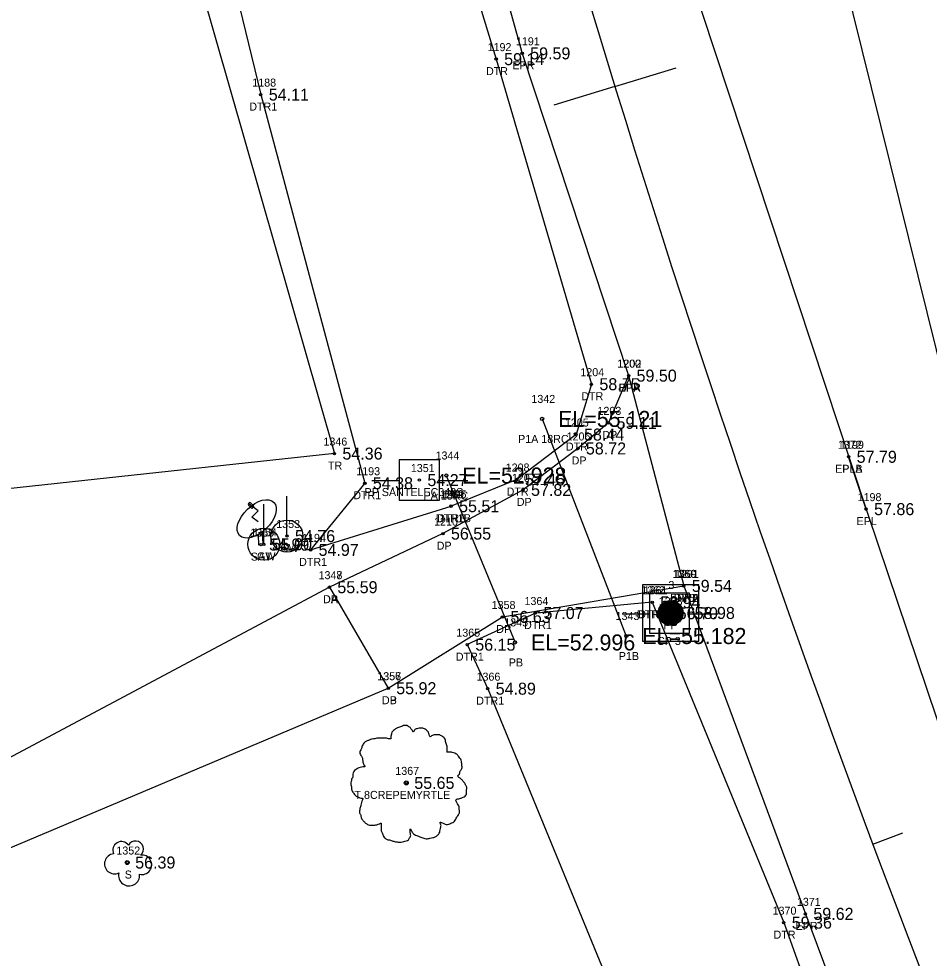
# Model space of a CAD drawing. Extents: x 2396531 to 2397633, y 770203 to 772837.
# Drawn here: x 2397010.1 to 2397123.8, y 771166.1 to 771283.5 of the extents above; entities that cross this region are included whole.
import ezdxf

# ---------------------------------------------------------------- set-up
doc = ezdxf.new("R2010")
doc.units = 0
for name, color, linetype in [('RD_EX_BldgApp', 7, 'Continuous'), ('RD_EX_BldgApp_txCode', 7, 'Continuous'), ('RD_EX_DR_Pipe', 7, 'Continuous'), ('RD_EX_DR_Pipe_txCode', 7, 'Continuous'), ('RD_EX_Driveway', 7, 'Continuous'), ('RD_EX_Driveway_txCode', 7, 'Continuous'), ('RD_EX_H2O', 7, 'Continuous'), ('RD_EX_H2O_txCode', 7, 'Continuous'), ('RD_EX_Road', 7, 'Continuous'), ('RD_EX_Road_txCode', 7, 'Continuous'), ('RD_EX_TX_BldgApp_ELEV', 7, 'Continuous'), ('RD_EX_TX_Driveway_ELEV', 7, 'Continuous'), ('RD_EX_TX_H2O_ELEV', 7, 'Continuous'), ('RD_EX_TX_Road_ELEV', 7, 'Continuous'), ('RD_EX_TX_UT_ELEV', 7, 'Continuous'), ('RD_EX_TX_VEG_ELEV', 7, 'Continuous'), ('RD_EX_UT', 7, 'Continuous'), ('RD_EX_UT_txCode', 7, 'Continuous'), ('RD_EX_VEG', 7, 'Continuous'), ('RD_EX_VEG_txCode', 7, 'Continuous'), ('RD_HC_Cl', 7, 'Continuous'), ('RD_HC_Data_Tic', 7, 'Continuous'), ('RD_HC_Survey', 7, 'Continuous'), ('RD_HC_Survey_ELEV', 7, 'Continuous'), ('RD_HC_Survey_txCode', 7, 'Continuous'), ('RD_SMD_Locator', 7, 'Continuous'), ('RD_TX_Pipe_ElevEX', 7, 'Continuous')]:
    doc.layers.add(name, color=color, linetype=linetype)

msp = doc.modelspace()

# ---------------------------------------------------------------- linework, layer by layer
at = {"layer": 'RD_EX_BldgApp'}
for p, q in [((2397039.18, 771222.31), (2397038.79, 771222.69)), ((2397039.97, 771221.99), (2397038.86, 771222.83)), ((2397039.03, 771222.99), (2397039.46, 771222.62)), ((2397039.07, 771222.73), (2397039.07, 771222.73)), ((2397039.18, 771222.71), (2397039.18, 771222.71)), ((2397039.46, 771222.62), (2397039.18, 771222.31)), ((2397039.2, 771221.22), (2397039.97, 771221.99)), ((2397039.97, 771220.61), (2397039.2, 771221.22)), ((2397039.97, 771219.05), (2397040.04, 771217.7)), ((2397040.5, 771219.33), (2397040.58, 771217.88))]:
    msp.add_line(p, q, dxfattribs=at)
msp.add_ellipse((2397039.81, 771220.99), major_axis=(-2.15, -2.07), ratio=0.564687, dxfattribs=at)
msp.add_ellipse((2397038.92, 771222.84), major_axis=(0.099, 0.164), ratio=0.846225, start_param=6.138676, end_param=9.218032, dxfattribs=at)
at = {"layer": 'RD_EX_DR_Pipe'}
for p, q in [((2397075.46, 771233.48), (2397085.98, 771206.36)), ((2397063.49, 771226.41), (2397072.08, 771205.56))]:
    msp.add_line(p, q, dxfattribs=at)
at = {"layer": 'RD_EX_Driveway'}
for p, q in [((2397048.88, 771212.46), (2397001.22, 771187.05)), ((2397003.63, 771177.66), (2397056.23, 771199.84))]:
    msp.add_line(p, q, dxfattribs=at)
msp.add_lwpolyline([(2397086.26, 771238.89), (2397083.76, 771232.99), (2397079.93, 771229.79), (2397073.08, 771224.62), (2397063.07, 771219.15), (2397048.88, 771212.46), (2397056.23, 771199.84), (2397070.51, 771208.74), (2397093.16, 771212.62)], dxfattribs=at)
at = {"layer": 'RD_EX_H2O'}
for points in [[(2397018.97, 771356.22), (2397026.87, 771329.32), (2397040.31, 771274), (2397053.31, 771225.45), (2397046.53, 771217.12), (2397064.09, 771222.58)], [(2397050.12, 771356.42), (2397048.45, 771348.09), (2397069.72, 771278.43), (2397081.62, 771237.82), (2397079.7, 771231.53), (2397072.3, 771225.91), (2397064.09, 771222.58)], [(2397089.23, 771210.58), (2397074.63, 771209.23), (2397066.11, 771205.28), (2397068.66, 771199.78), (2397083.54, 771163.57), (2397098.64, 771123.33)], [(2397089.23, 771210.58), (2397105.65, 771170.55), (2397119.48, 771131.94), (2397110.45, 771123.52), (2397093.81, 771116.52), (2397098.64, 771123.33)]]:
    msp.add_lwpolyline(points, dxfattribs=at)
at = {"layer": 'RD_EX_Road'}
for points in [[(2397072.37, 771363.69), (2397093.67, 771289.64), (2397115.94, 771222.21), (2397113.76, 771228.75)], [(2397051, 771358.07), (2397072.97, 771279.15), (2397086.26, 771238.89), (2397093.16, 771212.62)], [(2397113.76, 771228.75), (2397130.87, 771177.98), (2397154.19, 771118.49), (2397170.38, 771081.25), (2397178.53, 771063.49), (2397207.96, 771004.56), (2397238.54, 770949.11), (2397245.72, 770936.59), (2397280.76, 770876.73)], [(2397093.16, 771212.62), (2397108.35, 771171.65), (2397122.66, 771133.29), (2397131.66, 771109.5), (2397159.86, 771046.96), (2397187.02, 770992.86), (2397227.29, 770920.43), (2397260.16, 770864.73)]]:
    msp.add_lwpolyline(points, dxfattribs=at)
at = {"layer": 'RD_EX_UT'}
for p, q in [((2397062.62, 771228.35), (2397057.62, 771228.35)), ((2397057.62, 771228.35), (2397057.62, 771223.35)), ((2397062.62, 771223.35), (2397062.62, 771228.35)), ((2397054.19, 771225.79), (2397057.66, 771225.79)), ((2397062.55, 771225.79), (2397066.19, 771225.79)), ((2397043.58, 771218.85), (2397043.58, 771223.85)), ((2397057.62, 771223.35), (2397062.62, 771223.35)), ((2397040.69, 771217.82), (2397040.69, 771222.82)), ((2397093.89, 771211.72), (2397088.89, 771211.72)), ((2397088.89, 771211.72), (2397088.89, 771206.72)), ((2397093.89, 771206.72), (2397093.89, 771211.72)), ((2397085.46, 771209.15), (2397088.92, 771209.15)), ((2397093.82, 771209.15), (2397097.46, 771209.15)), ((2397088.89, 771206.72), (2397093.89, 771206.72))]:
    msp.add_line(p, q, dxfattribs=at)
for centre in [(2397040.69, 771217.82), (2397043.58, 771218.85)]:
    msp.add_circle(centre, 2, dxfattribs=at)
at = {"layer": 'RD_EX_VEG'}
for points in [[(2396666.35, 772324.52), (2396746.5, 772348.13), (2396878.43, 771953.6), (2396907.83, 771806.94), (2396910.04, 771736.08), (2396945.43, 771592.11), (2397049.51, 771229.15), (2396980.16, 771221.67)], [(2397137.17, 771710.16), (2397010.6, 771680.28), (2397078.29, 771429.37), (2397127.02, 771232.69), (2397127.02, 771232.69), (2397166.52, 771123.83), (2397178.02, 771098.29), (2397254.06, 771102.5)]]:
    msp.add_lwpolyline(points, dxfattribs=at)
for centre, radius in [((2397058.49, 771188.01), 0.25), ((2397058.48, 771187.99), 0.0001), ((2397023.62, 771178.06), 0.25)]:
    msp.add_circle(centre, radius, dxfattribs=at)
for centre, radius, start, end in [((2397022.9, 771179.6), 1.08, 34.9763, 204.756), ((2397024.66, 771179.76), 0.995, 308.7626, 152.0467), ((2397022.05, 771177.9), 1.26, 96.4518, 294.734), ((2397025.46, 771177.78), 1.22, 256.5667, 98.1046), ((2397023.86, 771176.46), 1.32, 166.8827, 5.7589)]:
    msp.add_arc(centre, radius, start, end, dxfattribs=at)
for points in [[(2397058.62, 771195.18), (2397058.32, 771195.2), (2397058, 771195.1), (2397057.75, 771195), (2397057.52, 771194.93), (2397057.3, 771194.83), (2397057, 771194.65), (2397056.77, 771194.45), (2397056.65, 771194.2), (2397056.6, 771193.98), (2397056.55, 771193.7), (2397056.55, 771193.53), (2397056.42, 771193.5), (2397056.27, 771193.53), (2397056.02, 771193.6), (2397055.77, 771193.6), (2397055.52, 771193.6), (2397055.17, 771193.58), (2397054.83, 771193.58), (2397054.55, 771193.53), (2397054.23, 771193.48), (2397053.85, 771193.35), (2397053.5, 771193.23), (2397053.2, 771192.98), (2397052.95, 771192.5), (2397052.83, 771192.15), (2397052.68, 771191.9), (2397052.83, 771191.45), (2397053, 771191.11), (2397053.03, 771190.91), (2397053.1, 771190.48), (2397053.2, 771190.26), (2397053.33, 771190.06), (2397053.25, 771190.03), (2397052.88, 771189.98), (2397052.58, 771189.88), (2397052.15, 771189.66), (2397051.93, 771189.43), (2397051.83, 771189.11), (2397051.8, 771188.76), (2397051.7, 771188.56), (2397051.63, 771188.28), (2397051.6, 771188.21), (2397051.55, 771187.88), (2397051.65, 771187.43), (2397051.68, 771187.08), (2397051.8, 771186.86), (2397051.95, 771186.68), (2397052.13, 771186.43), (2397052.53, 771186.21), (2397052.85, 771186.11), (2397053.05, 771186.08), (2397052.88, 771185.58), (2397052.83, 771185.23), (2397052.7, 771184.83), (2397052.7, 771184.76), (2397052.65, 771184.28), (2397052.8, 771183.96), (2397052.88, 771183.58), (2397053.05, 771183.36), (2397053.33, 771183.06), (2397053.65, 771182.83), (2397054.15, 771182.71), (2397054.55, 771182.73), (2397055.13, 771182.91), (2397055.37, 771182.98), (2397055.35, 771182.81), (2397055.37, 771182.43), (2397055.37, 771182.01), (2397055.52, 771181.68), (2397055.62, 771181.41), (2397055.77, 771181.16), (2397056.1, 771180.93), (2397056.5, 771180.86), (2397056.92, 771180.71), (2397057.37, 771180.63), (2397057.87, 771180.61), (2397058.47, 771180.76), (2397058.75, 771180.88), (2397058.85, 771181.06), (2397059.05, 771181.43), (2397059, 771181.66), (2397059.02, 771182.26), (2397059.12, 771182.08), (2397059.3, 771181.73), (2397059.8, 771181.43), (2397060.2, 771181.26), (2397060.67, 771181.11), (2397060.97, 771181.03), (2397061.45, 771181.11), (2397061.82, 771181.18), (2397062.2, 771181.31), (2397062.5, 771181.58), (2397062.67, 771181.86), (2397062.72, 771182.13), (2397062.8, 771182.51), (2397062.85, 771182.68)], [(2397062.85, 771182.68), (2397062.77, 771182.86), (2397062.72, 771183.11), (2397062.8, 771183.08), (2397062.97, 771183.03), (2397063.25, 771182.91), (2397063.47, 771182.83), (2397063.8, 771182.86), (2397064.07, 771182.96), (2397064.52, 771183.23), (2397064.8, 771183.71), (2397065.07, 771184.11), (2397065.15, 771184.43), (2397065.1, 771184.66), (2397065.07, 771185.16), (2397064.87, 771185.41), (2397064.82, 771185.53), (2397064.72, 771185.93), (2397064.8, 771185.98), (2397065.07, 771186.03), (2397065.45, 771186.16), (2397065.72, 771186.28), (2397065.95, 771186.46), (2397066.02, 771186.68), (2397066, 771187.08), (2397066.05, 771187.48), (2397065.97, 771187.63), (2397065.87, 771187.78), (2397065.8, 771187.98), (2397065.65, 771188.13), (2397065.55, 771188.28), (2397065.45, 771188.38), (2397065.32, 771188.53), (2397065.15, 771188.66), (2397065, 771188.71), (2397064.95, 771188.86), (2397065.1, 771189.06), (2397065.15, 771189.16), (2397065.17, 771189.38), (2397065.4, 771189.73), (2397065.45, 771190.13), (2397065.4, 771190.56), (2397065.35, 771190.83), (2397065.2, 771191.11), (2397065, 771191.35), (2397064.87, 771191.53), (2397064.7, 771191.65), (2397064.37, 771191.78), (2397064.12, 771191.83), (2397063.77, 771191.83), (2397063.57, 771191.88), (2397063.6, 771191.93), (2397063.6, 771192.08), (2397063.6, 771192.35), (2397063.52, 771192.8), (2397063.37, 771193.3), (2397063.37, 771193.33), (2397063.27, 771193.58), (2397063.05, 771193.78), (2397062.87, 771193.88), (2397062.67, 771194), (2397062.42, 771194.03), (2397062.12, 771194.03), (2397061.85, 771193.98), (2397061.65, 771193.88), (2397061.47, 771193.75), (2397061.4, 771193.9), (2397061.3, 771194.2), (2397061.25, 771194.35), (2397061.1, 771194.53), (2397060.87, 771194.73), (2397060.42, 771194.85), (2397059.8, 771194.78), (2397059.5, 771194.58), (2397059.35, 771194.4), (2397059.3, 771194.53), (2397059.1, 771194.73), (2397059, 771194.9), (2397058.82, 771195.03), (2397058.67, 771195.13), (2397058.57, 771195.18)]]:
    msp.add_spline(points, degree=3, dxfattribs=at)
at = {"layer": 'RD_HC_Cl'}
msp.add_arc((2398682.18, 771766.08), 1671.39, 194.59125, 211.50817, dxfattribs=at)
at = {"layer": 'RD_HC_Data_Tic'}
for p, q in [((2397084.56, 771275.01), (2397092.21, 771277.36)), ((2397084.56, 771275.01), (2397076.92, 771272.66)), ((2397116.79, 771180.36), (2397120.53, 771181.76))]:
    msp.add_line(p, q, dxfattribs=at)
at = {"layer": 'RD_HC_Survey'}
for p, q in [((2397090.51, 771208.06), (2397090.51, 771210.42)), ((2397090.56, 771208.02), (2397090.56, 771210.46)), ((2397090.61, 771207.98), (2397090.61, 771210.5)), ((2397090.66, 771207.94), (2397090.66, 771210.53)), ((2397090.71, 771207.91), (2397090.71, 771210.56)), ((2397090.76, 771207.88), (2397090.76, 771210.59)), ((2397090.81, 771207.86), (2397090.81, 771210.62)), ((2397090.86, 771207.83), (2397090.86, 771210.64)), ((2397090.91, 771207.81), (2397090.91, 771210.67)), ((2397090.96, 771207.79), (2397090.96, 771210.69)), ((2397091.01, 771207.77), (2397091.01, 771210.71)), ((2397091.06, 771207.75), (2397091.06, 771210.72)), ((2397091.11, 771207.74), (2397091.11, 771210.74)), ((2397091.16, 771207.73), (2397091.16, 771210.75)), ((2397091.21, 771207.71), (2397091.21, 771210.76)), ((2397091.26, 771207.7), (2397091.26, 771210.77)), ((2397091.31, 771207.7), (2397091.31, 771210.78)), ((2397091.36, 771207.69), (2397091.36, 771210.78)), ((2397091.41, 771207.69), (2397091.41, 771210.79)), ((2397091.46, 771207.68), (2397091.46, 771210.79)), ((2397091.51, 771207.68), (2397091.51, 771210.79)), ((2397091.56, 771207.68), (2397091.56, 771210.79)), ((2397091.61, 771207.69), (2397091.61, 771210.79)), ((2397091.66, 771207.69), (2397091.66, 771210.79)), ((2397091.71, 771207.69), (2397091.71, 771210.78)), ((2397091.76, 771207.7), (2397091.76, 771210.77)), ((2397091.81, 771207.71), (2397091.81, 771210.76)), ((2397091.86, 771207.72), (2397091.86, 771210.75)), ((2397091.91, 771207.73), (2397091.91, 771210.74)), ((2397091.96, 771207.75), (2397091.96, 771210.73)), ((2397092.01, 771207.76), (2397092.01, 771210.71)), ((2397092.06, 771207.78), (2397092.06, 771210.7)), ((2397092.11, 771207.8), (2397092.11, 771210.68)), ((2397092.16, 771207.82), (2397092.16, 771210.65)), ((2397092.21, 771207.84), (2397092.21, 771210.63)), ((2397092.26, 771207.87), (2397092.26, 771210.61)), ((2397092.31, 771207.9), (2397092.31, 771210.58)), ((2397092.36, 771207.93), (2397092.36, 771210.55)), ((2397092.41, 771207.96), (2397092.41, 771210.51)), ((2397092.46, 771208), (2397092.46, 771210.48)), ((2397092.51, 771208.04), (2397092.51, 771210.44)), ((2397092.56, 771208.08), (2397092.56, 771210.39)), ((2397090.01, 771208.88), (2397090.01, 771209.6)), ((2397090.06, 771208.71), (2397090.06, 771209.77)), ((2397090.11, 771208.59), (2397090.11, 771209.89)), ((2397090.16, 771208.49), (2397090.16, 771209.99)), ((2397090.21, 771208.4), (2397090.21, 771210.07)), ((2397090.26, 771208.33), (2397090.26, 771210.15)), ((2397090.31, 771208.26), (2397090.31, 771210.21)), ((2397090.36, 771208.2), (2397090.36, 771210.27)), ((2397090.41, 771208.15), (2397090.41, 771210.32)), ((2397090.46, 771208.1), (2397090.46, 771210.37)), ((2397092.61, 771208.13), (2397092.61, 771210.35)), ((2397092.66, 771208.18), (2397092.66, 771210.3)), ((2397092.71, 771208.23), (2397092.71, 771210.24)), ((2397092.76, 771208.3), (2397092.76, 771210.18)), ((2397092.81, 771208.37), (2397092.81, 771210.11)), ((2397092.86, 771208.45), (2397092.86, 771210.03)), ((2397092.91, 771208.54), (2397092.91, 771209.94)), ((2397092.96, 771208.65), (2397092.96, 771209.83)), ((2397093.01, 771208.79), (2397093.01, 771209.69)), ((2397093.06, 771209.01), (2397093.06, 771209.46))]:
    msp.add_line(p, q, dxfattribs=at)
msp.add_lwpolyline([(2397095.06, 771212.77), (2397087.99, 771212.77), (2397087.99, 771205.7), (2397095.06, 771205.7)], close=True, dxfattribs=at)
msp.add_circle((2397091.52, 771209.24), 1.55, dxfattribs=at)
at = {"layer": 'RD_SMD_Locator'}
for centre, radius in [((2397069.72, 771278.43), 0.15), ((2397072.97, 771279.15), 0.15), ((2397040.31, 771274), 0.15), ((2397086.26, 771238.89), 0.15), ((2397086.26, 771238.89), 0.15), ((2397081.62, 771237.82), 0.15), ((2397075.46, 771233.48), 0.2), ((2397083.76, 771232.99), 0.15), ((2397079.7, 771231.53), 0.15), ((2397049.51, 771229.15), 0.15), ((2397079.93, 771229.79), 0.15), ((2397113.76, 771228.75), 0.15), ((2397113.76, 771228.75), 0.15), ((2397060.13, 771225.84), 0.15), ((2397063.49, 771226.41), 0.2), ((2397072.3, 771225.91), 0.15), ((2397053.31, 771225.45), 0.15), ((2397073.08, 771224.62), 0.15), ((2397064.09, 771222.58), 0.15), ((2397064.09, 771222.58), 0.15), ((2397115.94, 771222.21), 0.15), ((2397043.58, 771218.85), 0.15), ((2397063.07, 771219.15), 0.15), ((2397040.35, 771217.78), 0.15), ((2397040.69, 771217.82), 0.15), ((2397046.53, 771217.12), 0.15), ((2397093.16, 771212.62), 0.15), ((2397093.16, 771212.62), 0.15), ((2397093.16, 771212.62), 0.15), ((2397048.88, 771212.46), 0.15), ((2397048.88, 771212.46), 0.15), ((2397089.23, 771210.58), 0.15), ((2397089.23, 771210.58), 0.15), ((2397074.63, 771209.23), 0.15), ((2397091.4, 771209.21), 0.15), ((2397091.52, 771209.24), 0.15), ((2397070.51, 771208.74), 0.15), ((2397072.08, 771205.56), 0.2), ((2397085.98, 771206.36), 0.2), ((2397066.11, 771205.28), 0.15), ((2397056.23, 771199.84), 0.15), ((2397056.23, 771199.84), 0.15), ((2397068.66, 771199.78), 0.15), ((2397058.49, 771188.01), 0.15), ((2397023.62, 771178.06), 0.15), ((2397108.35, 771171.65), 0.15), ((2397105.65, 771170.55), 0.15)]:
    msp.add_circle(centre, radius, dxfattribs=at)

# ---------------------------------------------------------------- texts
at = {"layer": 'RD_EX_BldgApp_txCode'}
for s, p in [('1355', (2397039, 771218.78)), ('SAT', (2397039.06, 771215.78))]:
    msp.add_text(s, height=1, dxfattribs=at).set_placement(p)
at = {"layer": 'RD_EX_DR_Pipe_txCode'}
for s, p in [('1342', (2397074.12, 771235.48)), ('P1A 18RC', (2397072.46, 771230.48)), ('1344', (2397062.15, 771228.41)), ('PA 18RC', (2397060.65, 771223.41)), ('1343', (2397084.64, 771208.36)), ('1345', (2397070.73, 771207.56)), ('PB', (2397071.3, 771202.56)), ('P1B', (2397085.04, 771203.36))]:
    msp.add_text(s, height=1, dxfattribs=at).set_placement(p)
at = {"layer": 'RD_EX_Driveway_txCode'}
for s, p in [('1202', (2397084.88, 771239.89)), ('DPA', (2397085, 771236.89)), ('1203', (2397082.38, 771233.99)), ('1206', (2397078.52, 771230.79)), ('DP', (2397082.98, 771230.99)), ('DP', (2397079.15, 771227.79)), ('1207', (2397071.69, 771225.62)), ('DP', (2397072.3, 771222.62)), ('1210', (2397061.97, 771220.15)), ('DP', (2397062.29, 771217.15)), ('1347', (2397047.53, 771213.46)), ('1348', (2397047.53, 771213.46)), ('1359', (2397091.81, 771213.62)), ('DPB', (2397091.9, 771210.62)), ('DA', (2397048.08, 771210.46)), ('DP', (2397048.1, 771210.46)), ('1358', (2397069.16, 771209.74)), ('DP', (2397069.73, 771206.74)), ('1356', (2397054.86, 771200.84)), ('1357', (2397054.88, 771200.84)), ('DB', (2397055.45, 771197.84)), ('DP', (2397055.45, 771197.84))]:
    msp.add_text(s, height=1, dxfattribs=at).set_placement(p)
at = {"layer": 'RD_EX_H2O_txCode'}
for s, p in [('1192', (2397068.65, 771279.43)), ('DTR', (2397068.45, 771276.43)), ('1188', (2397039.25, 771275)), ('DTR1', (2397038.88, 771272)), ('1204', (2397080.24, 771238.82)), ('DTR', (2397080.36, 771235.82)), ('1205', (2397078.31, 771232.53)), ('DTR', (2397078.43, 771229.53)), ('1193', (2397052.24, 771226.45)), ('1208', (2397070.91, 771226.91)), ('1209', (2397062.71, 771223.58)), ('1195', (2397063.03, 771223.58)), ('DTR', (2397071.03, 771223.91)), ('DTR1', (2397051.87, 771223.45)), ('DTR1B', (2397062.19, 771220.58)), ('DTRB', (2397062.35, 771220.58)), ('1194', (2397045.47, 771218.12)), ('DTR1', (2397045.1, 771215.12)), ('1362', (2397087.86, 771211.58)), ('1361', (2397088.14, 771211.58)), ('1364', (2397073.26, 771210.23)), ('DTR1A', (2397087.31, 771208.58)), ('DTRA', (2397087.47, 771208.58)), ('DTR1', (2397073.2, 771207.23)), ('1365', (2397064.74, 771206.28)), ('DTR1', (2397064.68, 771203.28)), ('1366', (2397067.27, 771200.78)), ('DTR1', (2397067.23, 771197.78)), ('1370', (2397104.26, 771171.55)), ('DTR', (2397104.38, 771168.55))]:
    msp.add_text(s, height=1, dxfattribs=at).set_placement(p)
at = {"layer": 'RD_EX_Road_txCode'}
for s, p in [('1191', (2397072.19, 771280.15)), ('EPR', (2397071.75, 771277.15)), ('1200', (2397084.84, 771239.89)), ('EPR', (2397085.04, 771236.89)), ('1372', (2397112.41, 771229.75)), ('1199', (2397112.69, 771229.75)), ('EPLA', (2397112.06, 771226.75)), ('EPLB', (2397112.08, 771226.75)), ('1198', (2397114.88, 771223.21)), ('EPL', (2397114.74, 771220.21)), ('1360', (2397091.75, 771213.62)), ('1201', (2397092.05, 771213.62)), ('EPRA', (2397091.44, 771210.62)), ('EPRB', (2397091.46, 771210.62)), ('1371', (2397107.29, 771172.65)), ('EPR', (2397107.12, 771169.65))]:
    msp.add_text(s, height=1, dxfattribs=at).set_placement(p)
at = {"layer": 'RD_EX_TX_BldgApp_ELEV'}
msp.add_text('54.99', height=1.5, dxfattribs=at).set_placement((2397041.35, 771217.03))
at = {"layer": 'RD_EX_TX_Driveway_ELEV'}
for s, p in [('59.50', (2397087.26, 771238.14)), ('59.11', (2397084.76, 771232.24)), ('58.72', (2397080.93, 771229.04)), ('57.82', (2397074.08, 771223.87)), ('56.55', (2397064.07, 771218.4)), ('55.59', (2397049.88, 771211.71)), ('55.59', (2397049.88, 771211.71)), ('59.54', (2397094.16, 771211.87)), ('56.63', (2397071.51, 771207.99)), ('55.92', (2397057.23, 771199.09)), ('55.92', (2397057.23, 771199.09))]:
    msp.add_text(s, height=1.5, dxfattribs=at).set_placement(p)
at = {"layer": 'RD_EX_TX_H2O_ELEV'}
for s, p in [('59.14', (2397070.72, 771277.68)), ('54.11', (2397041.31, 771273.25)), ('58.75', (2397082.62, 771237.07)), ('58.44', (2397080.7, 771230.78)), ('54.38', (2397054.31, 771224.7)), ('57.45', (2397073.3, 771225.16)), ('55.51', (2397065.09, 771221.83)), ('55.51', (2397065.09, 771221.83)), ('54.97', (2397047.53, 771216.37)), ('58.94', (2397090.23, 771209.83)), ('58.94', (2397090.23, 771209.83)), ('57.07', (2397075.63, 771208.48)), ('56.15', (2397067.11, 771204.53)), ('54.89', (2397069.66, 771199.03)), ('59.36', (2397106.65, 771169.8))]:
    msp.add_text(s, height=1.5, dxfattribs=at).set_placement(p)
at = {"layer": 'RD_EX_TX_Road_ELEV'}
for s, p in [('59.59', (2397073.97, 771278.4)), ('59.50', (2397087.26, 771238.14)), ('57.79', (2397114.76, 771228)), ('57.79', (2397114.76, 771228)), ('57.86', (2397116.94, 771221.46)), ('59.54', (2397094.16, 771211.87)), ('59.54', (2397094.16, 771211.87)), ('59.62', (2397109.35, 771170.9))]:
    msp.add_text(s, height=1.5, dxfattribs=at).set_placement(p)
at = {"layer": 'RD_EX_TX_UT_ELEV'}
for s, p in [('54.76', (2397044.58, 771218.1)), ('55.00', (2397041.69, 771217.07))]:
    msp.add_text(s, height=1.5, dxfattribs=at).set_placement(p)
at = {"layer": 'RD_EX_TX_VEG_ELEV'}
for s, p in [('54.36', (2397050.51, 771228.4)), ('55.65', (2397059.49, 771187.26)), ('56.39', (2397024.62, 771177.31))]:
    msp.add_text(s, height=1.5, dxfattribs=at).set_placement(p)
at = {"layer": 'RD_EX_UT_txCode'}
for s, p in [('1351', (2397059.06, 771226.84)), ('PP SANTELEC048S', (2397053.28, 771223.84)), ('1354', (2397039.34, 771218.82)), ('1353', (2397042.24, 771219.85)), ('GW', (2397042.74, 771216.85)), ('GW', (2397039.85, 771215.82)), ('1268', (2397090.03, 771210.21)), ('PP', (2397090.62, 771207.21))]:
    msp.add_text(s, height=1, dxfattribs=at).set_placement(p)
at = {"layer": 'RD_EX_VEG_txCode'}
for s, p in [('1346', (2397048.14, 771230.15)), ('TR', (2397048.71, 771227.15)), ('1367', (2397057.12, 771189.01)), ('T 8CREPEMYRTLE', (2397052.02, 771186.01)), ('1352', (2397022.27, 771179.06)), ('S', (2397023.31, 771176.06))]:
    msp.add_text(s, height=1, dxfattribs=at).set_placement(p)
at = {"layer": 'RD_HC_Survey_ELEV'}
for s, p in [('54.27', (2397061.13, 771225.09)), ('56.70', (2397092.4, 771208.46)), ('58.98', (2397094.52, 771208.49))]:
    msp.add_text(s, height=1.5, dxfattribs=at).set_placement(p)
at = {"layer": 'RD_HC_Survey_txCode'}
for s, p in [('3', (2397091.24, 771212.24)), ('CP 3', (2397089.82, 771205.24))]:
    msp.add_text(s, height=1, dxfattribs=at).set_placement(p)
at = {"layer": 'RD_TX_Pipe_ElevEX'}
for s, p in [('EL=55.121', (2397077.46, 771232.48)), ('EL=52.928', (2397065.49, 771225.41)), ('EL=55.182', (2397087.98, 771205.36)), ('EL=52.996', (2397074.08, 771204.56))]:
    msp.add_text(s, height=2, dxfattribs=at).set_placement(p)

doc.saveas('drawing.dxf')
